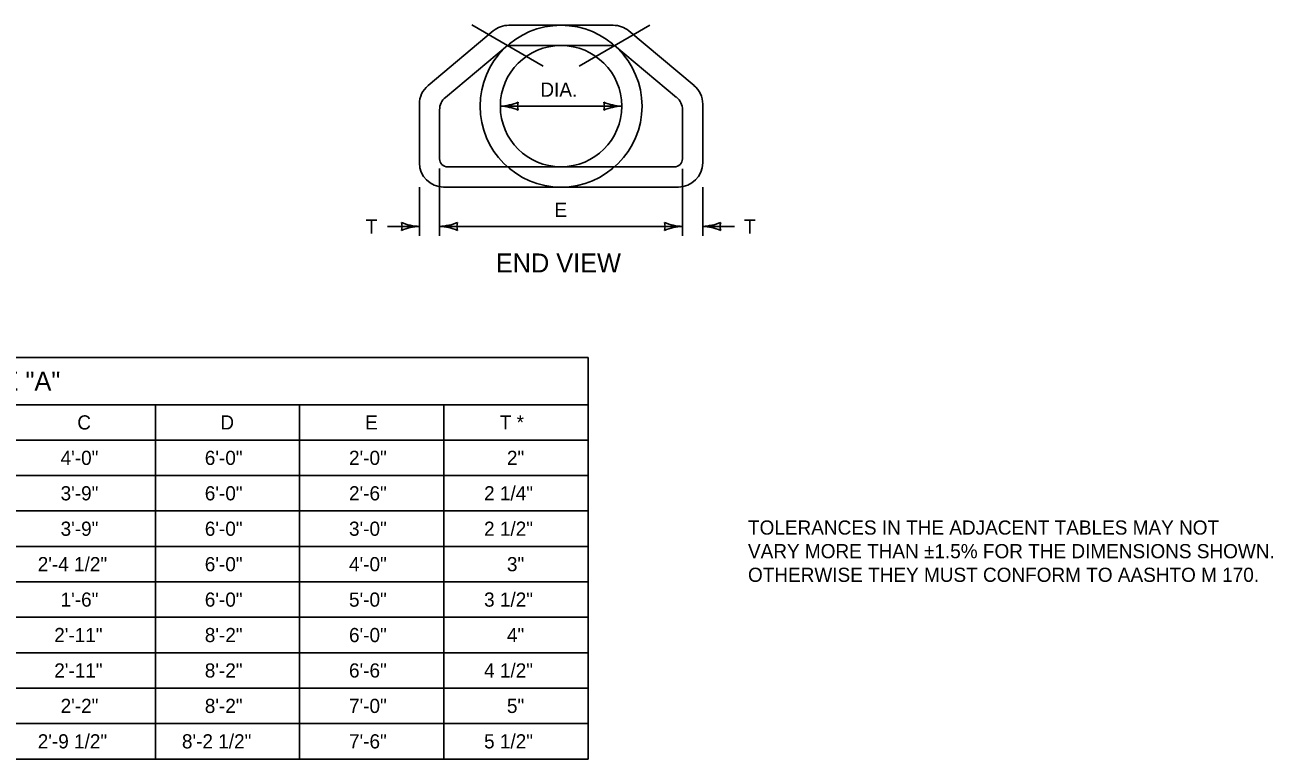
# Model space of a CAD drawing. Extents: x 49991.4 to 50021, y 49987.6 to 50011.4.
# Drawn here: x 50003.23 to 50008.51, y 49992.98 to 49996.08 of the extents above; entities that cross this region are included whole.
import ezdxf

# ---------------------------------------------------------------- set-up
doc = ezdxf.new("R2010")
doc.units = 0
for name, color, linetype in [('Level 1', 7, 'Continuous'), ('Level 2', 7, 'Continuous'), ('Level 3', 7, 'Continuous'), ('Level 4', 7, 'Continuous'), ('Level 5', 7, 'Continuous')]:
    doc.layers.add(name, color=color, linetype=linetype)

msp = doc.modelspace()

# ---------------------------------------------------------------- linework, layer by layer
at = {"layer": 'Level 1'}
for p, q in [((50005.278, 49996.083), (50005.7191, 49996.083)), ((50005.2121, 49996.0591), (50004.9361, 49995.828)), ((50005.7851, 49996.0591), (50006.0611, 49995.828)), ((50005.2717, 49995.9973), (50005.0093, 49995.7777)), ((50005.2723, 49995.9973), (50005.725, 49995.9973)), ((50005.7253, 49995.9973), (50005.9877, 49995.7777)), ((50004.8992, 49995.7492), (50004.8992, 49995.5009)), ((50004.9849, 49995.7252), (50004.9849, 49995.518)), ((50006.0122, 49995.7252), (50006.0122, 49995.518)), ((50006.0979, 49995.7492), (50006.0979, 49995.5009)), ((50005.0191, 49995.4837), (50005.978, 49995.4837)), ((50005.002, 49995.3981), (50005.9951, 49995.3981))]:
    msp.add_line(p, q, dxfattribs=at)
msp.add_circle((50005.4986, 49995.7405), 0.2568, dxfattribs=at)
for centre, radius, start, end in [((50005.278, 49995.9803), 0.1027, 90, 129.9017), ((50005.7191, 49995.9803), 0.1027, 50.0941, 90), ((50005.002, 49995.7492), 0.1027, 129.9211, 180), ((50005.9951, 49995.7493), 0.1027, 0, 50.0781), ((50005.0534, 49995.7252), 0.0685, 129.9484, 180), ((50005.9438, 49995.7252), 0.0685, 0, 50.0789), ((50005.002, 49995.5008), 0.1027, 180, 270), ((50005.0191, 49995.5179), 0.0342, 180, 270), ((50005.978, 49995.5179), 0.0342, 270, 0), ((50005.9951, 49995.5008), 0.1027, 270, 0)]:
    msp.add_arc(centre, radius, start, end, dxfattribs=at)
at = {"layer": 'Level 2'}
for p, q in [((50000.7327, 49994.677), (50005.6127, 49994.677)), ((50005.6127, 49994.677), (50005.6127, 49992.977)), ((50005.6127, 49994.677), (50005.6127, 49992.977)), ((50000.7327, 49994.477), (50005.6127, 49994.477)), ((50003.7827, 49994.477), (50003.7827, 49992.977)), ((50004.3927, 49994.477), (50004.3927, 49992.977)), ((50005.0027, 49994.477), (50005.0027, 49992.977)), ((50000.7327, 49994.327), (50005.6127, 49994.327)), ((50000.7327, 49994.177), (50005.6127, 49994.177)), ((50000.7327, 49994.027), (50005.6127, 49994.027)), ((50000.7327, 49993.877), (50005.6127, 49993.877)), ((50000.7327, 49993.727), (50005.6127, 49993.727)), ((50000.7327, 49993.577), (50005.6127, 49993.577)), ((50000.7327, 49993.427), (50005.6127, 49993.427)), ((50000.7327, 49993.277), (50005.6127, 49993.277)), ((50000.7327, 49993.127), (50005.6127, 49993.127)), ((50000.7327, 49992.977), (50005.6127, 49992.977))]:
    msp.add_line(p, q, dxfattribs=at)
at = {"layer": 'Level 3'}
for p, q in [((50005.2417, 49995.7406), (50005.7554, 49995.7406)), ((50004.9849, 49995.4767), (50004.9849, 49995.1915)), ((50006.0122, 49995.4757), (50006.0122, 49995.1915)), ((50004.8993, 49995.3981), (50004.8993, 49995.1915)), ((50006.0979, 49995.3981), (50006.0979, 49995.1915)), ((50004.8993, 49995.2315), (50004.7644, 49995.2315)), ((50004.9849, 49995.2315), (50006.0122, 49995.2315)), ((50006.2328, 49995.2315), (50006.0979, 49995.2315))]:
    msp.add_line(p, q, dxfattribs=at)
for centre, radius, start, end in [((50005.2302, 49995.9733), 0.233, 272.8273, 292.0772), ((50005.2326, 49995.5185), 0.2223, 67.456, 87.6395), ((50005.3699, 49995.7406), 0.0548, 162.1388, 197.8612), ((50005.7646, 49995.9627), 0.2223, 247.456, 267.6395), ((50005.6272, 49995.7406), 0.0548, 342.1388, 17.8612), ((50005.7669, 49995.5079), 0.233, 92.8273, 112.0772), ((50004.9085, 49995.4536), 0.2223, 247.456, 267.6395), ((50004.7711, 49995.2315), 0.0548, 342.1388, 17.8612), ((50004.9108, 49994.9988), 0.233, 92.8273, 112.0772), ((50004.9734, 49995.4642), 0.233, 272.8273, 292.0772), ((50004.9757, 49995.0094), 0.2223, 67.456, 87.6395), ((50005.1131, 49995.2315), 0.0548, 162.1388, 197.8612), ((50006.0214, 49995.4536), 0.2223, 247.456, 267.6395), ((50005.884, 49995.2315), 0.0548, 342.1388, 17.8612), ((50006.0237, 49994.9988), 0.233, 92.8273, 112.0772), ((50006.0864, 49995.4642), 0.233, 272.8273, 292.0772), ((50006.0887, 49995.0094), 0.2223, 67.456, 87.6395), ((50006.2261, 49995.2315), 0.0548, 162.1388, 197.8612)]:
    msp.add_arc(centre, radius, start, end, dxfattribs=at)
at = {"layer": 'Level 4'}
msp.add_circle((50005.4986, 49995.7405), 0.3425, dxfattribs=at)
at = {"layer": 'Level 5'}
for p, q in [((50005.423, 49995.9103), (50005.1216, 49996.0844)), ((50005.575, 49995.9105), (50005.8746, 49996.0836))]:
    msp.add_line(p, q, dxfattribs=at)

# ---------------------------------------------------------------- texts
at = {"layer": 'Level 2'}
for s, height, p in [('DIA.', 0.06, (50005.4111, 49995.7806)), ('E', 0.06, (50005.4706, 49995.2715)), ('T', 0.06, (50004.6724, 49995.2015)), ('T', 0.06, (50006.2728, 49995.2015)), ('END VIEW', 0.08, (50005.2229, 49995.037)), ('TYPE "A"', 0.08, (50002.9239, 49994.537)), ('C', 0.06, (50003.4522, 49994.372)), ('D', 0.06, (50004.0574, 49994.372)), ('E', 0.06, (50004.6697, 49994.372)), ('T *', 0.06, (50005.2395, 49994.372)), ('4\'-0"', 0.06, (50003.3816, 49994.222)), ('6\'-0"', 0.06, (50003.9916, 49994.222)), ('2\'-0"', 0.06, (50004.6016, 49994.222)), ('2"', 0.06, (50005.2697, 49994.222)), ('3\'-9"', 0.06, (50003.3816, 49994.072)), ('6\'-0"', 0.06, (50003.9916, 49994.072)), ('2\'-6"', 0.06, (50004.6016, 49994.072)), ('2 1/4"', 0.06, (50005.173, 49994.072)), ('3\'-9"', 0.06, (50003.3816, 49993.922)), ('6\'-0"', 0.06, (50003.9916, 49993.922)), ('3\'-0"', 0.06, (50004.6016, 49993.922)), ('2 1/2"', 0.06, (50005.173, 49993.922)), ('TOLERANCES IN THE ADJACENT TABLES MAY NOT', 0.06, (50006.2895, 49993.927)), ('VARY MORE THAN ±1.5% FOR THE DIMENSIONS SHOWN.', 0.06, (50006.2895, 49993.827)), ('2\'-4 1/2"', 0.06, (50003.2849, 49993.772)), ('6\'-0"', 0.06, (50003.9916, 49993.772)), ('4\'-0"', 0.06, (50004.6016, 49993.772)), ('3"', 0.06, (50005.2697, 49993.772)), ('OTHERWISE THEY MUST CONFORM TO AASHTO M 170.', 0.06, (50006.2895, 49993.727)), ('1\'-6"', 0.06, (50003.3816, 49993.622)), ('6\'-0"', 0.06, (50003.9916, 49993.622)), ('5\'-0"', 0.06, (50004.6016, 49993.622)), ('3 1/2"', 0.06, (50005.173, 49993.622)), ('2\'-11"', 0.06, (50003.3546, 49993.472)), ('8\'-2"', 0.06, (50003.9916, 49993.472)), ('6\'-0"', 0.06, (50004.6016, 49993.472)), ('4"', 0.06, (50005.2697, 49993.472)), ('2\'-11"', 0.06, (50003.3547, 49993.322)), ('8\'-2"', 0.06, (50003.9916, 49993.322)), ('6\'-6"', 0.06, (50004.6016, 49993.322)), ('4 1/2"', 0.06, (50005.173, 49993.322)), ('2\'-2"', 0.06, (50003.3816, 49993.172)), ('8\'-2"', 0.06, (50003.9916, 49993.172)), ('7\'-0"', 0.06, (50004.6016, 49993.172)), ('5"', 0.06, (50005.2697, 49993.172)), ('2\'-9 1/2"', 0.06, (50003.2849, 49993.022)), ('8\'-2 1/2"', 0.06, (50003.8949, 49993.022)), ('7\'-6"', 0.06, (50004.6016, 49993.022)), ('5 1/2"', 0.06, (50005.173, 49993.022))]:
    msp.add_text(s, height=height, dxfattribs=at).set_placement(p)

doc.saveas('drawing.dxf')
